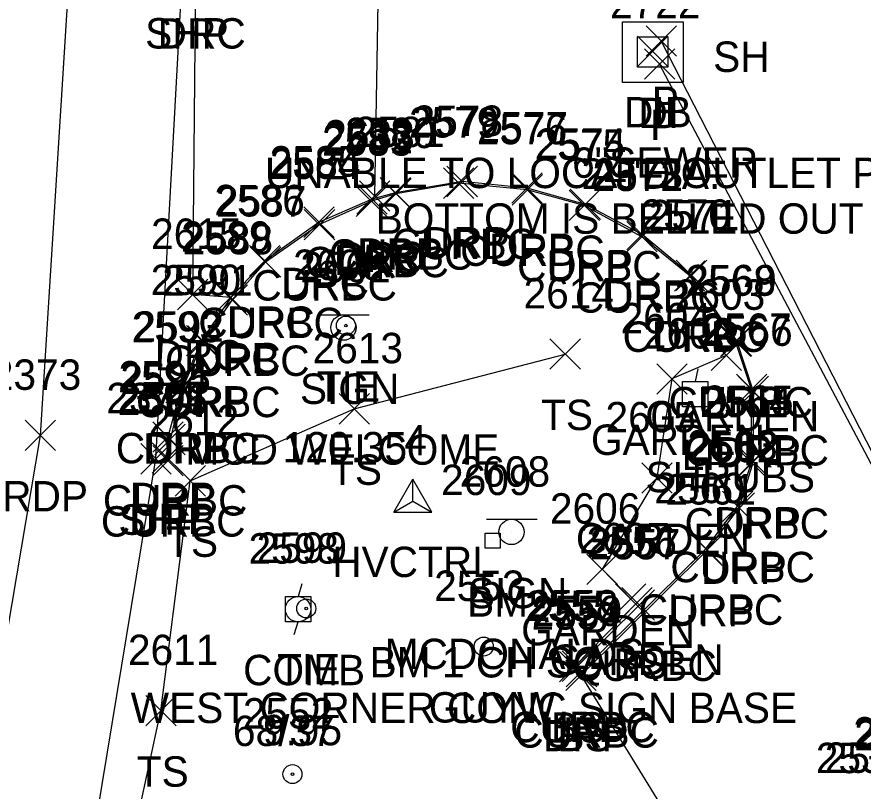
# Model space of a CAD drawing. Extents: x 1769141 to 1770911, y 735471 to 741449.
# Drawn here: x 1770641.7 to 1770697.4, y 737045 to 737095.9 of the extents above; entities that cross this region are included whole.
import ezdxf

# ---------------------------------------------------------------- set-up
doc = ezdxf.new("R2010")
doc.units = 0
for name, color, linetype in [('C_A', 7, 'Continuous'), ('C_C', 7, 'Continuous'), ('C_I', 7, 'Continuous'), ('CBP', 7, 'Continuous'), ('CPBM', 7, 'Continuous'), ('CPSM', 7, 'Continuous'), ('D_A', 7, 'Continuous'), ('D_C', 7, 'Continuous'), ('D_I', 7, 'Continuous'), ('D_TIC', 7, 'Continuous'), ('DCP', 7, 'Continuous'), ('DS', 7, 'Continuous'), ('L_A', 7, 'Continuous'), ('L_C', 7, 'Continuous'), ('L_I', 7, 'Continuous'), ('L_TIC', 7, 'Continuous'), ('LAPB', 7, 'Continuous'), ('LELB', 7, 'Continuous'), ('P_A', 7, 'Continuous'), ('P_I', 7, 'Continuous'), ('P_TIC', 7, 'Continuous'), ('PET', 7, 'Continuous'), ('PSP', 7, 'Continuous'), ('R_A', 7, 'Continuous'), ('R_I', 7, 'Continuous'), ('R_TIC', 7, 'Continuous'), ('RC', 7, 'Continuous'), ('RDP', 7, 'Continuous'), ('S_A', 7, 'Continuous'), ('S_C', 7, 'Continuous'), ('S_I', 7, 'Continuous'), ('SSGN', 7, 'Continuous'), ('U_A', 7, 'Continuous'), ('U_C', 7, 'Continuous'), ('U_I', 7, 'Continuous'), ('ULP', 7, 'Continuous'), ('UP', 7, 'Continuous'), ('UPGW', 7, 'Continuous')]:
    doc.layers.add(name, color=color, linetype=linetype)

msp = doc.modelspace()

# ---------------------------------------------------------------- linework, layer by layer
at = {"layer": 'CBP'}
for centre, radius in [((1770663.336, 737075.576), 0.625), ((1770663.336, 737075.576), 0.0833), ((1770660.728, 737056.967), 0.625), ((1770660.728, 737056.967), 0.0833)]:
    msp.add_circle(centre, radius, dxfattribs=at)
at = {"layer": 'CPBM'}
for p, q in [((1770672.487, 737060.926), (1770672.487, 737061.926)), ((1770672.487, 737061.926), (1770673.487, 737061.926)), ((1770673.487, 737061.926), (1770673.487, 737060.926)), ((1770672.99, 737061.427), (1770672.99, 737061.427)), ((1770672.99, 737061.427), (1770672.99, 737061.427)), ((1770673.487, 737060.926), (1770672.487, 737060.926))]:
    msp.add_line(p, q, dxfattribs=at)
at = {"layer": 'CPSM'}
for p, q in [((1770666.491, 737063.31), (1770667.741, 737065.475)), ((1770668.991, 737063.31), (1770667.741, 737065.475)), ((1770667.741, 737064.031), (1770667.741, 737065.475)), ((1770666.491, 737063.31), (1770667.741, 737064.031)), ((1770667.741, 737064.031), (1770667.741, 737064.031)), ((1770667.741, 737064.031), (1770668.991, 737063.31)), ((1770666.491, 737063.31), (1770668.991, 737063.31))]:
    msp.add_line(p, q, dxfattribs=at)
at = {"layer": 'D_TIC'}
for points in [[(1770683.079, 737093.297), (1770685.079, 737095.297)], [(1770685.079, 737093.297), (1770683.079, 737095.297)], [(1770682.523, 737092.618), (1770684.523, 737094.618)], [(1770684.523, 737092.618), (1770682.523, 737094.618)], [(1770682.97, 737091.779), (1770684.97, 737093.779)], [(1770684.97, 737091.779), (1770682.97, 737093.779)]]:
    msp.add_lwpolyline(points, dxfattribs=at)
at = {"layer": 'DCP'}
for points in [[(1770714.561, 737034.874), (1770684.079, 737094.297)], [(1770713.779, 737036.471), (1770683.97, 737092.779)]]:
    msp.add_lwpolyline(points, dxfattribs=at)
at = {"layer": 'DS'}
for p, q in [((1770681.523, 737095.567), (1770685.523, 737095.567)), ((1770681.523, 737091.567), (1770681.523, 737095.567)), ((1770685.523, 737095.567), (1770685.523, 737091.567)), ((1770682.523, 737092.567), (1770682.523, 737094.567)), ((1770682.523, 737094.567), (1770684.523, 737094.567)), ((1770684.523, 737094.567), (1770684.523, 737092.567)), ((1770683.528, 737093.568), (1770683.528, 737093.568)), ((1770683.528, 737093.568), (1770683.528, 737093.568)), ((1770684.523, 737092.567), (1770682.523, 737092.567)), ((1770685.523, 737091.567), (1770681.523, 737091.567))]:
    msp.add_line(p, q, dxfattribs=at)
at = {"layer": 'L_TIC'}
for points in [[(1770676.761, 737072.701), (1770678.761, 737074.701)], [(1770678.761, 737072.701), (1770676.761, 737074.701)], [(1770687.356, 737072.612), (1770689.356, 737074.612)], [(1770689.356, 737072.612), (1770687.356, 737074.612)], [(1770683.786, 737071.067), (1770685.786, 737073.067)], [(1770685.786, 737071.067), (1770683.786, 737073.067)], [(1770662.884, 737069.098), (1770664.884, 737071.098)], [(1770664.884, 737069.098), (1770662.884, 737071.098)], [(1770652.102, 737064.362), (1770654.102, 737066.362)], [(1770654.102, 737064.362), (1770652.102, 737066.362)], [(1770682.797, 737064.551), (1770684.797, 737066.551)], [(1770684.797, 737064.551), (1770682.797, 737066.551)], [(1770679.195, 737058.546), (1770681.195, 737060.546)], [(1770681.195, 737058.546), (1770679.195, 737060.546)], [(1770681.068, 737056.597), (1770683.068, 737058.597)], [(1770683.068, 737056.597), (1770681.068, 737058.597)], [(1770681.478, 737056.34), (1770683.478, 737058.34)], [(1770683.478, 737056.34), (1770681.478, 737058.34)], [(1770677.384, 737052.141), (1770679.384, 737054.141)], [(1770679.384, 737052.141), (1770677.384, 737054.141)], [(1770677.807, 737051.575), (1770679.807, 737053.575)], [(1770679.807, 737051.575), (1770677.807, 737053.575)], [(1770650.171, 737049.241), (1770652.171, 737051.241)], [(1770652.171, 737049.241), (1770650.171, 737051.241)]]:
    msp.add_lwpolyline(points, dxfattribs=at)
at = {"layer": 'LAPB'}
msp.add_lwpolyline([(1770688.356, 737073.612), (1770684.786, 737072.067), (1770683.797, 737065.551), (1770680.195, 737059.546), (1770682.068, 737057.597)], dxfattribs=at)
at = {"layer": 'LELB'}
for points in [[(1770647.732, 737034.389), (1770651.171, 737050.241), (1770653.102, 737065.362), (1770663.884, 737070.098), (1770677.761, 737073.701)], [(1770678.807, 737052.575), (1770678.384, 737053.141), (1770682.478, 737057.34)]]:
    msp.add_lwpolyline(points, dxfattribs=at)
at = {"layer": 'P_TIC'}
for points in [[(1770642.239, 737067.348), (1770644.239, 737069.348)], [(1770644.239, 737067.348), (1770642.239, 737069.348)], [(1770649.838, 737065.811), (1770651.838, 737067.811)], [(1770651.838, 737065.811), (1770649.838, 737067.811)]]:
    msp.add_lwpolyline(points, dxfattribs=at)
at = {"layer": 'PET'}
msp.add_lwpolyline([(1770275.701, 736500.443), (1770293.456, 736523.994), (1770308.246, 736544.527), (1770339.602, 736585.989), (1770354.041, 736607.647), (1770377.094, 736638.846), (1770405.465, 736677.522), (1770433.078, 736714.634), (1770457.829, 736747.118), (1770487.075, 736785.889), (1770511.852, 736818.72), (1770532.144, 736846.484), (1770557.142, 736879.905), (1770576.719, 736906.621), (1770599.363, 736940.91), (1770615.19, 736970.363), (1770629.485, 737005.853), (1770638.546, 737040.65), (1770643.239, 737068.348), (1770645.294, 737100.928), (1770643.286, 737138.022), (1770637.483, 737178.199), (1770623.12, 737230.101), (1770608.302, 737274.144)], dxfattribs=at)
at = {"layer": 'PSP'}
msp.add_lwpolyline([(1770340.145, 736567.061), (1770355.712, 736595.48), (1770384.336, 736632.07), (1770413.376, 736670.654), (1770426.21, 736690.901), (1770435.181, 736712.82), (1770460.126, 736745.306), (1770489.927, 736784.126), (1770514.631, 736816.065), (1770535.698, 736843.486), (1770560.973, 736877.108), (1770581.175, 736903.184), (1770605.599, 736937.839), (1770621.173, 736966.95), (1770635.97, 737003.978), (1770646.024, 737037.66), (1770650.838, 737066.811), (1770652.594, 737098.802), (1770650.922, 737139.651), (1770647.506, 737164.146), (1770640.683, 737197.771), (1770629.066, 737231.113), (1770614.088, 737275.469)], dxfattribs=at)
at = {"layer": 'R_TIC'}
for points in [[(1770669.985, 737084.052), (1770671.985, 737086.052)], [(1770671.985, 737084.052), (1770669.985, 737086.052)], [(1770669.751, 737083.945), (1770671.751, 737085.945)], [(1770671.751, 737083.945), (1770669.751, 737085.945)], [(1770674.257, 737083.624), (1770676.257, 737085.624)], [(1770676.257, 737083.624), (1770674.257, 737085.624)], [(1770674.266, 737083.503), (1770676.266, 737085.503)], [(1770676.266, 737083.503), (1770674.266, 737085.503)], [(1770664.224, 737083.092), (1770666.224, 737085.092)], [(1770666.224, 737083.092), (1770664.224, 737085.092)], [(1770665.582, 737083.317), (1770667.582, 737085.317)], [(1770667.582, 737083.317), (1770665.582, 737085.317)], [(1770665.63, 737083.25), (1770667.63, 737085.25)], [(1770667.63, 737083.25), (1770665.63, 737085.25)], [(1770664.022, 737082.754), (1770666.022, 737084.754)], [(1770666.022, 737082.754), (1770664.022, 737084.754)], [(1770664.055, 737082.897), (1770666.055, 737084.897)], [(1770666.055, 737082.897), (1770664.055, 737084.897)], [(1770664.055, 737082.897), (1770666.055, 737084.897)], [(1770666.055, 737082.897), (1770664.055, 737084.897)], [(1770678.013, 737082.483), (1770680.013, 737084.483)], [(1770680.013, 737082.483), (1770678.013, 737084.483)], [(1770678.087, 737082.546), (1770680.087, 737084.546)], [(1770680.087, 737082.546), (1770678.087, 737084.546)], [(1770660.574, 737081.378), (1770662.574, 737083.378)], [(1770662.574, 737081.378), (1770660.574, 737083.378)], [(1770660.6, 737081.222), (1770662.6, 737083.222)], [(1770662.6, 737081.222), (1770660.6, 737083.222)], [(1770681.813, 737080.424), (1770683.813, 737082.424)], [(1770683.813, 737080.424), (1770681.813, 737082.424)], [(1770681.826, 737080.562), (1770683.826, 737082.562)], [(1770683.826, 737080.562), (1770681.826, 737082.562)], [(1770656.998, 737078.833), (1770658.998, 737080.833)], [(1770658.998, 737078.833), (1770656.998, 737080.833)], [(1770657.047, 737078.75), (1770659.047, 737080.75)], [(1770659.047, 737078.75), (1770657.047, 737080.75)], [(1770684.954, 737077.845), (1770686.954, 737079.845)], [(1770686.954, 737077.845), (1770684.954, 737079.845)], [(1770685.068, 737077.874), (1770687.068, 737079.874)], [(1770687.068, 737077.874), (1770685.068, 737079.874)], [(1770652.26, 737076.621), (1770654.26, 737078.621)], [(1770654.26, 737076.621), (1770652.26, 737078.621)], [(1770654.759, 737076.427), (1770656.759, 737078.427)], [(1770656.759, 737076.427), (1770654.759, 737078.427)], [(1770654.759, 737076.427), (1770656.759, 737078.427)], [(1770656.759, 737076.427), (1770654.759, 737078.427)], [(1770654.855, 737076.264), (1770656.855, 737078.264)], [(1770656.855, 737076.264), (1770654.855, 737078.264)], [(1770652.842, 737073.59), (1770654.842, 737075.59)], [(1770654.842, 737073.59), (1770652.842, 737075.59)], [(1770652.948, 737073.551), (1770654.948, 737075.551)], [(1770654.948, 737073.551), (1770652.948, 737075.551)], [(1770687.974, 737073.534), (1770689.974, 737075.534)], [(1770689.974, 737073.534), (1770687.974, 737075.534)], [(1770688.046, 737073.569), (1770690.046, 737075.569)], [(1770690.046, 737073.569), (1770688.046, 737075.569)], [(1770651.499, 737070.483), (1770653.499, 737072.483)], [(1770653.499, 737070.483), (1770651.499, 737072.483)], [(1770651.617, 737070.515), (1770653.617, 737072.515)], [(1770653.617, 737070.515), (1770651.617, 737072.515)], [(1770689.022, 737070.372), (1770691.022, 737072.372)], [(1770691.022, 737070.372), (1770689.022, 737072.372)], [(1770689.14, 737070.24), (1770691.14, 737072.24)], [(1770691.14, 737070.24), (1770689.14, 737072.24)], [(1770650.633, 737067.239), (1770652.633, 737069.239)], [(1770652.633, 737067.239), (1770650.633, 737069.239)], [(1770650.766, 737067.079), (1770652.766, 737069.079)], [(1770652.766, 737067.079), (1770650.766, 737069.079)], [(1770650.585, 737065.868), (1770652.585, 737067.868)], [(1770652.585, 737065.868), (1770650.585, 737067.868)], [(1770650.638, 737065.693), (1770652.638, 737067.693)], [(1770652.638, 737065.693), (1770650.638, 737067.693)], [(1770689.027, 737065.565), (1770691.027, 737067.565)], [(1770691.027, 737065.565), (1770689.027, 737067.565)], [(1770689.143, 737065.631), (1770691.143, 737067.631)], [(1770691.143, 737065.631), (1770689.143, 737067.631)], [(1770688.098, 737062.692), (1770690.098, 737064.692)], [(1770690.098, 737062.692), (1770688.098, 737064.692)], [(1770688.208, 737062.583), (1770690.208, 737064.583)], [(1770690.208, 737062.583), (1770688.208, 737064.583)], [(1770686.017, 737059.892), (1770688.017, 737061.892)], [(1770688.017, 737059.892), (1770686.017, 737061.892)], [(1770686.094, 737059.801), (1770688.094, 737061.801)], [(1770688.094, 737059.801), (1770686.094, 737061.801)], [(1770681.639, 737056.198), (1770683.639, 737058.198)], [(1770683.639, 737056.198), (1770681.639, 737058.198)], [(1770677.561, 737052.171), (1770679.561, 737054.171)], [(1770679.561, 737052.171), (1770677.561, 737054.171)], [(1770677.836, 737051.81), (1770679.836, 737053.81)], [(1770679.836, 737051.81), (1770677.836, 737053.81)], [(1770677.807, 737051.575), (1770679.807, 737053.575)], [(1770679.807, 737051.575), (1770677.807, 737053.575)]]:
    msp.add_lwpolyline(points, dxfattribs=at)
at = {"layer": 'RC'}
msp.add_lwpolyline([(1770682.639, 737057.198), (1770678.561, 737053.171), (1770678.836, 737052.81), (1770687.017, 737060.892), (1770689.098, 737063.692), (1770690.027, 737066.565), (1770690.022, 737071.372), (1770688.974, 737074.534), (1770685.954, 737078.845), (1770682.813, 737081.424), (1770679.013, 737083.483), (1770675.266, 737084.503), (1770670.751, 737084.945), (1770666.63, 737084.25), (1770665.022, 737083.754), (1770661.6, 737082.222), (1770658.047, 737079.75), (1770655.855, 737077.264), (1770653.948, 737074.551), (1770652.617, 737071.515), (1770651.766, 737068.079), (1770651.638, 737066.693)], dxfattribs=at)
at = {"layer": 'RDP'}
for points in [[(1770665.055, 737083.897), (1770661.574, 737082.378), (1770657.998, 737079.833), (1770655.759, 737077.427), (1770653.26, 737077.621), (1770653.462, 737098.798), (1770654.204, 737130.595), (1770657.248, 737130.808), (1770659.725, 737128.229), (1770662.614, 737126.256), (1770665.886, 737124.928), (1770665.567, 737104.49), (1770665.224, 737084.092)], [(1770697.526, 737043.153), (1770693.796, 737039.663), (1770689.521, 737035.175), (1770678.807, 737052.575), (1770687.094, 737060.801), (1770689.208, 737063.583), (1770690.143, 737066.631), (1770690.14, 737071.24), (1770689.046, 737074.569), (1770686.068, 737078.874), (1770682.826, 737081.562), (1770679.087, 737083.546), (1770675.257, 737084.624), (1770670.985, 737085.052), (1770666.582, 737084.317), (1770665.055, 737083.897)], [(1770655.759, 737077.427), (1770653.842, 737074.59), (1770652.499, 737071.483), (1770651.633, 737068.239), (1770651.585, 737066.868)]]:
    msp.add_lwpolyline(points, dxfattribs=at)
at = {"layer": 'SSGN'}
for p, q in [((1770661.528, 737076.275), (1770664.861, 737076.275)), ((1770663.175, 737075.442), (1770663.175, 737075.442)), ((1770672.58, 737062.831), (1770675.913, 737062.831)), ((1770674.227, 737061.998), (1770674.227, 737061.998))]:
    msp.add_line(p, q, dxfattribs=at)
for centre in [(1770663.175, 737075.442), (1770674.227, 737061.998)]:
    msp.add_circle(centre, 0.833, dxfattribs=at)
at = {"layer": 'ULP'}
for p, q in [((1770686.485, 737072.732), (1770686.318, 737071.899)), ((1770685.485, 737070.232), (1770685.485, 737071.899)), ((1770685.485, 737071.899), (1770687.151, 737071.899)), ((1770687.151, 737071.899), (1770687.151, 737070.232)), ((1770686.318, 737071.066), (1770686.318, 737071.066)), ((1770687.151, 737070.232), (1770685.485, 737070.232)), ((1770686.068, 737069.399), (1770686.318, 737070.232))]:
    msp.add_line(p, q, dxfattribs=at)
at = {"layer": 'UP'}
for p, q in [((1770660.439, 737058.584), (1770660.189, 737057.751)), ((1770659.355, 737056.084), (1770659.355, 737057.751)), ((1770659.355, 737057.751), (1770661.022, 737057.751)), ((1770661.022, 737057.751), (1770661.022, 737056.084)), ((1770660.189, 737056.917), (1770660.189, 737056.917)), ((1770661.022, 737056.084), (1770659.355, 737056.084)), ((1770659.939, 737055.251), (1770660.189, 737056.084))]:
    msp.add_line(p, q, dxfattribs=at)
msp.add_circle((1770660.189, 737056.917), 0.833, dxfattribs=at)
at = {"layer": 'UPGW'}
for centre, radius in [((1770672.4, 737054.461), 0.625), ((1770672.4, 737054.461), 0.0833), ((1770659.821, 737046.069), 0.625), ((1770659.821, 737046.069), 0.0833)]:
    msp.add_circle(centre, radius, dxfattribs=at)

# ---------------------------------------------------------------- texts
at = {"layer": 'C_A'}
for s, p in [('TIE', (1770661.415, 737070.576)), ('HVCTRL', (1770662.434, 737059.031)), ('BM', (1770671.305, 737056.427)), ('TIE', (1770658.806, 737051.967))]:
    msp.add_text(s, height=2, dxfattribs=at).set_placement(p)
at = {"layer": 'C_C'}
for s, p in [('120.35', (1770659.179, 737066.576)), ('BM 1 CH SQ', (1770664.895, 737052.427)), ('WEST CORNER CONC SIGN BASE', (1770649.179, 737049.427)), ('9.95', (1770657.877, 737047.967))]:
    msp.add_text(s, height=2, dxfattribs=at).set_placement(p)
at = {"layer": 'C_I'}
for s, p in [('2600', (1770659.864, 737078.576)), ('4', (1770667.174, 737067.031)), ('2609', (1770669.596, 737064.427)), ('2599', (1770657.46, 737059.967))]:
    msp.add_text(s, height=2, dxfattribs=at).set_placement(p)
at = {"layer": 'D_A'}
for s, p in [('P', (1770683.457, 737089.297)), ('DIB', (1770681.626, 737088.618)), ('DI', (1770682.583, 737088.568)), ('P', (1770683.348, 737087.779))]:
    msp.add_text(s, height=2, dxfattribs=at).set_placement(p)
at = {"layer": 'D_C'}
for s, p in [('6"SEWER', (1770678.213, 737085.297)), ('UNABLE TO LOCATE OUTLET PIPE', (1770658.011, 737084.618)), ('24"DIA.', (1770678.835, 737084.568)), ('BOTTOM IS BELLED OUT', (1770665.295, 737081.618))]:
    msp.add_text(s, height=2, dxfattribs=at).set_placement(p)
at = {"layer": 'D_I'}
msp.add_text('2722', height=2, dxfattribs=at).set_placement((1770680.71, 737095.779))
at = {"layer": 'L_A'}
for s, p in [('SH', (1770687.493, 737092.263)), ('TS', (1770676.17, 737068.701)), ('GARDEN', (1770683.026, 737068.612)), ('GARDEN', (1770679.455, 737067.067)), ('TS', (1770662.294, 737065.098)), ('TS', (1770651.511, 737060.362)), ('GARDEN', (1770678.467, 737060.551)), ('GARDEN', (1770674.865, 737054.546)), ('GARDEN', (1770676.737, 737052.597)), ('BS', (1770680.919, 737052.34)), ('BS', (1770676.825, 737048.141)), ('BS', (1770677.248, 737047.575)), ('TS', (1770649.58, 737045.241))]:
    msp.add_text(s, height=2, dxfattribs=at).set_placement(p)
at = {"layer": 'L_C'}
msp.add_text('SHRUBS', height=2, dxfattribs=at).set_placement((1770683.049, 737064.612))
at = {"layer": 'L_I'}
for s, p in [('2614', (1770675.021, 737076.701)), ('2603', (1770684.97, 737076.612)), ('2604', (1770681.4, 737075.067)), ('2613', (1770661.144, 737073.098)), ('2605', (1770680.412, 737068.551)), ('2612', (1770650.362, 737068.362)), ('2606', (1770676.755, 737062.546)), ('2607', (1770678.682, 737060.597)), ('2556', (1770679.163, 737060.34)), ('2555', (1770675.124, 737056.141)), ('2554', (1770675.547, 737055.575)), ('2611', (1770648.998, 737053.241))]:
    msp.add_text(s, height=2, dxfattribs=at).set_placement(p)
at = {"layer": 'P_A'}
for s, p in [('SHP', (1770650.13, 737093.802)), ('RDP', (1770640.727, 737063.348)), ('SHP', (1770648.373, 737061.811))]:
    msp.add_text(s, height=2, dxfattribs=at).set_placement(p)
at = {"layer": 'P_I'}
for s, p in [('2373', (1770639.979, 737071.348)), ('2374', (1770647.578, 737069.811))]:
    msp.add_text(s, height=2, dxfattribs=at).set_placement(p)
at = {"layer": 'R_A'}
for s, p in [('DRC', (1770650.95, 737093.798)), ('CURBC', (1770666.334, 737079.945)), ('DRP', (1770668.474, 737080.052)), ('DRP', (1770672.746, 737079.624)), ('CURBC', (1770662.212, 737079.25)), ('DRC', (1770662.712, 737079.092)), ('DRP', (1770664.07, 737079.317)), ('CURBC', (1770670.848, 737079.503)), ('CURBC', (1770660.605, 737078.754)), ('DRC', (1770662.544, 737078.897)), ('DRP', (1770662.544, 737078.897)), ('CURBC', (1770674.596, 737078.483)), ('DRP', (1770676.575, 737078.546)), ('DRC', (1770659.063, 737077.378)), ('CURBC', (1770657.183, 737077.222)), ('CURBC', (1770678.396, 737076.424)), ('DRP', (1770680.314, 737076.562)), ('CURBC', (1770653.629, 737074.75)), ('DRC', (1770655.486, 737074.833)), ('CURBC', (1770681.537, 737073.845)), ('DRP', (1770683.556, 737073.874)), ('DRC', (1770650.748, 737072.621)), ('DRC', (1770653.247, 737072.427)), ('DRP', (1770653.247, 737072.427)), ('CURBC', (1770651.438, 737072.264)), ('CURBC', (1770649.531, 737069.551)), ('DRP', (1770651.33, 737069.59)), ('CURBC', (1770684.557, 737069.534)), ('DRP', (1770686.534, 737069.569)), ('CURBC', (1770648.2, 737066.515)), ('DRP', (1770649.987, 737066.483)), ('CURBC', (1770685.605, 737066.372)), ('DRP', (1770687.628, 737066.24)), ('CURBC', (1770647.349, 737063.079)), ('DRP', (1770649.121, 737063.239)), ('DRP', (1770649.074, 737061.868)), ('CURBC', (1770647.22, 737061.693)), ('CURBC', (1770685.61, 737061.565)), ('DRP', (1770687.631, 737061.631)), ('CURBC', (1770684.681, 737058.692)), ('DRP', (1770686.696, 737058.583)), ('CURBC', (1770682.6, 737055.892)), ('DRP', (1770684.582, 737055.801)), ('CURBC', (1770678.221, 737052.198)), ('CURBC', (1770674.144, 737048.171)), ('CURBC', (1770674.419, 737047.81)), ('DRP', (1770676.295, 737047.575))]:
    msp.add_text(s, height=2, dxfattribs=at).set_placement(p)
at = {"layer": 'R_I'}
for s, p in [('2579', (1770667.483, 737087.945)), ('2578', (1770667.726, 737088.052)), ('2576', (1770671.951, 737087.503)), ('2577', (1770671.998, 737087.624)), ('2582', (1770661.796, 737086.897)), ('2582', (1770661.796, 737086.897)), ('2633', (1770661.917, 737087.092)), ('2580', (1770663.283, 737087.25)), ('2581', (1770663.889, 737087.317)), ('2583', (1770661.762, 737086.754)), ('2575', (1770675.753, 737086.483)), ('2574', (1770675.827, 737086.546)), ('2585', (1770658.315, 737085.378)), ('2584', (1770658.34, 737085.222)), ('2572', (1770679.553, 737084.424)), ('2573', (1770679.566, 737084.562)), ('2586', (1770654.683, 737082.833)), ('2587', (1770654.787, 737082.75)), ('2570', (1770682.722, 737081.874)), ('2571', (1770683.261, 737081.845)), ('2615', (1770650.52, 737080.621)), ('2589', (1770652.491, 737080.427)), ('2589', (1770652.491, 737080.427)), ('2588', (1770652.595, 737080.264)), ('2590', (1770650.496, 737077.59)), ('2591', (1770651.255, 737077.551)), ('2568', (1770685.667, 737077.534)), ('2569', (1770685.731, 737077.569)), ('2593', (1770649.239, 737074.483)), ('2592', (1770649.358, 737074.515)), ('2567', (1770686.715, 737074.372)), ('2566', (1770686.777, 737074.24)), ('2594', (1770648.373, 737071.239)), ('2595', (1770648.506, 737071.079)), ('2596', (1770648.323, 737069.693)), ('2597', (1770648.326, 737069.868)), ('2564', (1770686.72, 737069.565)), ('2565', (1770686.835, 737069.631)), ('2563', (1770685.791, 737066.692)), ('2562', (1770685.901, 737066.583)), ('2560', (1770683.623, 737063.892)), ('2561', (1770684.353, 737063.801)), ('2557', (1770679.379, 737060.198)), ('2558', (1770675.301, 737056.171)), ('2559', (1770675.568, 737055.81)), ('2554', (1770675.547, 737055.575)), ('2528', (1770696.71, 737047.816)), ('2529', (1770696.776, 737047.633)), ('2530', (1770694.246, 737046.133)), ('2531', (1770694.833, 737046.153))]:
    msp.add_text(s, height=2, dxfattribs=at).set_placement(p)
at = {"layer": 'S_A'}
for p in [(1770660.313, 737070.421), (1770671.364, 737056.977)]:
    msp.add_text('SIGN', height=2, dxfattribs=at).set_placement(p)
at = {"layer": 'S_C'}
for s, p in [('MCD WELCOME', (1770652.777, 737066.421)), ('MCDONALDS', (1770665.892, 737052.977))]:
    msp.add_text(s, height=2, dxfattribs=at).set_placement(p)
at = {"layer": 'S_I'}
for s, p in [('2601', (1770660.336, 737078.421)), ('2608', (1770670.821, 737064.977))]:
    msp.add_text(s, height=2, dxfattribs=at).set_placement(p)
at = {"layer": 'U_A'}
for s, p in [('LI', (1770685.42, 737066.066)), ('COMB', (1770656.574, 737051.917)), ('GUYW', (1770668.794, 737049.461))]:
    msp.add_text(s, height=2, dxfattribs=at).set_placement(p)
at = {"layer": 'U_C'}
msp.add_text('68/37', height=2, dxfattribs=at).set_placement((1770655.905, 737047.917))
at = {"layer": 'U_I'}
for s, p in [('2602', (1770682.932, 737074.066)), ('2598', (1770656.929, 737059.917)), ('2553', (1770669.141, 737057.461)), ('2552', (1770656.561, 737049.069))]:
    msp.add_text(s, height=2, dxfattribs=at).set_placement(p)

doc.saveas('drawing.dxf')
